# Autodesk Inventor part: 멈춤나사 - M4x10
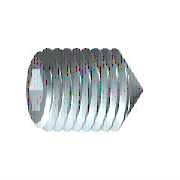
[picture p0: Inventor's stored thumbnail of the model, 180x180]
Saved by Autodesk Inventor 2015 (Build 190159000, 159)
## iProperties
Created: 2012-02
Part Number: 멈춤나사 - M4x10
Material: 강철, 연강
Description: 6각 소켓 머리 없는 멈춤 나사
Document SubType Name: Modeling
Standard: KS B 1028
Designer: mduedu
Standards Organization: KS
Language: ko-KR
Size Designation: 원추점 M4x10
Categories: <MemberInstance><Categories><Category DisplayName="조임쇠" InternalName="e4da775c-781d-43d5-af7c-5136215cf5a6" Mnemonic="FSTN"><Category DisplayName="볼트" InternalN
Density: 7.86 g/cm^3
Mass: 0.792069 g
Surface Area: 1.48192 cm^2
Volume: 0.100772 cm^3
Appearance: 강철
Author: mduedu
IsCustomPart: 1
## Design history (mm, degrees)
sketch "스케치1"
  geometry: L1 (0, 0)-(6.833, 0); L2 (10, 1.155)-(10, 2); L3 (10, 2)-(0, 2); L4 (10, 1.155)-(7.5, 1.155); L5 (7.5, 1.155)-(6.833, 0); L6 (0, -0.4)-(0, 2.4) reference; L7 (0, 2)-(0, 0)
  constraints: 13 end point, 3 parallel, 1 collinear, 1 perpendicular, 1 point on line
  dimensions: "d0" = 2.5 distance of L2.start L4.end (= INTI); "d1" = 60 deg angle of L5 L1; "d2" = 4 diameter of L3 L1 (= NND); "d3" = 2.3094 diameter of L4 L1 (= 1.1547 x SW); "d5" = 10 distance from line of L2 L3.end (= NLG)
revolve "본체" sketch "스케치1" stored, may be unused: angle "d6" = 90 deg
sketch "스케치2"
  geometry: L1 (-0.577, 1)-(0.577, 1); L2 (0.577, 1)-(1.155, 0); L3 (1.155, 0)-(0.577, -1); L4 (0.577, -1)-(-0.577, -1); L5 (-0.577, -1)-(-1.155, 0); L6 (-1.155, 0)-(-0.577, 1); 3 further points
  constraints: 12 end point, 1 coincident, 1 horizontal, 13 other
extrude "슬롯" join sketch "스케치2" taper "d7" = 0 deg; stored distance "d21" = 10
workaxis "Work Axis1"
workplane "Work Plane1"
sketch "스케치4"
  geometry: L1 (-5, 0.2)-(-3.2, 2) reference; L2 (-5, -0.2)-(-3.2, -2) reference; L3 (-3.2, 2)-(-5.2, 0); L4 (-3.2, -2)-(-5.2, 0); 2 further points
  constraints: 4 end point, 2 collinear, 1 coincident
body "Solid1"
feature "스레드" dims "d12" = 10 (= NLG), "d13" = 0
chamfer "모따기1" distance "d8" = 1.8 (computed from NND, SPD, FAWI); stored, may be unused: angle "d9" = 45 deg (= FAWI), second distance "d34" = 1.8 (computed from NND, SPD, FAWI)
chamfer "모따기2" distance "d10" = 0.42941 (= -0.5 x GD1 + 0.5 x NND); stored, may be unused: angle "d11" = 45 deg (= FAWI), second distance "d35" = 0.42941 (= -0.5 x GD1 + 0.5 x NND)
other parameters: "NND" = 4 [user parameter; used in 5 equation terms], "NLG" = 10 [user parameter; used in 2 equation terms], "INTI" = 2.5 [user parameter; used in 1 equation term], "FAWI" = 45 deg [user parameter; used in 4 equation terms], "SW" = 2 [user parameter; used in 2 equation terms], "GD1" = 3.14117 (= THREADDIA - 1.2269 x PTC) [user parameter; used in 2 equation terms], "d4" = 0, "FAWI1" = 45 deg [user parameter], "SPD" = 0.4 [user parameter; used in 2 equation terms], "d36" = 0, "d37" = 0, "GUL" = 0.42941 (= 0.61345 x PTC) [user parameter], "TPU" = 14.28571 (computed from PTC) [user parameter], "TOA" = 30 deg [user parameter], "THREADDIA" = 4 [user parameter; used in 1 equation term], "PTC" = 0.7 [user parameter; used in 4 equation terms], "GAL" = 0.42941 (= 0.61345 x PTC) [user parameter], "E0" = 2.31 (= 1.155 x SW) [user parameter]
